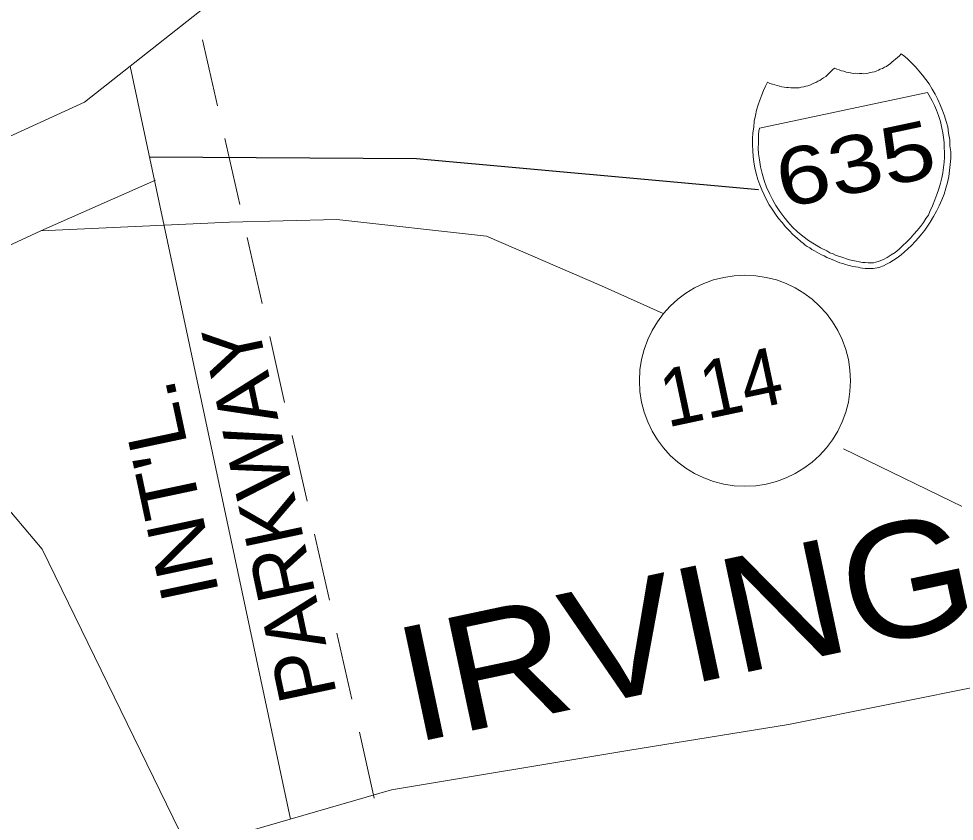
# Model space of a CAD drawing. Extents: x 2357218 to 2371708, y 6973728 to 6980157.
# Drawn here: x 2357598.1 to 2357681, y 6974748.1 to 6974819.3 of the extents above; entities that cross this region are included whole.
import ezdxf

# ---------------------------------------------------------------- set-up
doc = ezdxf.new("R2010")
doc.units = 0
doc.header["$LTSCALE"] = 2
doc.linetypes.add('MEDIUM_DASHED', pattern=[4.5, 3, -1.5])
doc.layers.add('62', color=7, linetype='Continuous', lineweight=13)
doc.layers.add('63', color=7, linetype='Continuous', lineweight=13)

msp = doc.modelspace()

# ---------------------------------------------------------------- linework, layer by layer
at = {"layer": '62', "linetype": 'MEDIUM_DASHED'}
msp.add_line((2357608.391, 6974843.78), (2357670.463, 6974569.716), dxfattribs=at)
at = {"layer": '62'}
for p, q in [((2357622.155, 6974748.291), (2357607.952, 6974815.115)), ((2357600.015, 6974800.5), (2357610.198, 6974804.988)), ((2357649.756, 6974795.612), (2357655.227, 6974793.141)), ((2357691.251, 6974771.4), (2357671.217, 6974781.127))]:
    msp.add_line(p, q, dxfattribs=at)
for points in [[(2357587.853, 6974800.146), (2357596.85, 6974808.683), (2357603.892, 6974811.906), (2357617.998, 6974823.047)], [(2357671.247, 6974814.652), (2357671.444, 6974814.579), (2357671.661, 6974814.533), (2357671.829, 6974814.499), (2357672.069, 6974814.457), (2357672.25, 6974814.474), (2357672.445, 6974814.424), (2357672.625, 6974814.44), (2357672.832, 6974814.437), (2357673.018, 6974814.431), (2357673.222, 6974814.451), (2357673.398, 6974814.488), (2357673.594, 6974814.53), (2357673.77, 6974814.566), (2357673.969, 6974814.61), (2357674.164, 6974814.673), (2357674.329, 6974814.754), (2357674.474, 6974814.831), (2357674.667, 6974814.896), (2357674.846, 6974815.026), (2357675.017, 6974815.085), (2357675.196, 6974815.214), (2357675.358, 6974815.319), (2357675.515, 6974815.444), (2357675.692, 6974815.596), (2357675.828, 6974815.716), (2357676.002, 6974815.87), (2357676.176, 6974816.02), (2357676.324, 6974816.191), (2357676.647, 6974815.959), (2357676.962, 6974815.682), (2357677.277, 6974815.381), (2357677.604, 6974815.036), (2357677.909, 6974814.687), (2357678.217, 6974814.317), (2357678.532, 6974813.922), (2357678.801, 6974813.52), (2357679.085, 6974813.05), (2357679.336, 6974812.622), (2357679.577, 6974812.143), (2357679.794, 6974811.659), (2357679.991, 6974811.174), (2357680.185, 6974810.686), (2357680.31, 6974810.205), (2357680.462, 6974809.709), (2357680.534, 6974809.148), (2357680.636, 6974808.574), (2357680.658, 6974808.027), (2357680.727, 6974807.489), (2357680.73, 6974806.938), (2357680.664, 6974806.372), (2357680.615, 6974805.853), (2357680.546, 6974805.311), (2357680.428, 6974804.779), (2357680.284, 6974804.266), (2357680.14, 6974803.75), (2357679.948, 6974803.25), (2357679.717, 6974802.718), (2357679.474, 6974802.229), (2357679.208, 6974801.757), (2357678.9, 6974801.255), (2357678.677, 6974800.908), (2357678.428, 6974800.557), (2357678.137, 6974800.196), (2357677.863, 6974799.862), (2357677.56, 6974799.542), (2357677.244, 6974799.201), (2357676.916, 6974798.901), (2357676.61, 6974798.606), (2357676.319, 6974798.362), (2357675.981, 6974798.104), (2357675.664, 6974797.874), (2357675.333, 6974797.691), (2357675.045, 6974797.535), (2357674.754, 6974797.383), (2357674.454, 6974797.274), (2357674.192, 6974797.217)], [(2357674.192, 6974797.217), (2357674.014, 6974797.18), (2357673.859, 6974797.147), (2357673.674, 6974797.152), (2357673.517, 6974797.143), (2357673.331, 6974797.151), (2357673.146, 6974797.156), (2357672.911, 6974797.176), (2357672.697, 6974797.2), (2357672.506, 6974797.251), (2357672.288, 6974797.297), (2357672.049, 6974797.336), (2357671.834, 6974797.382), (2357671.588, 6974797.447), (2357671.393, 6974797.497), (2357671.146, 6974797.583), (2357670.901, 6974797.646), (2357670.678, 6974797.735), (2357670.424, 6974797.841), (2357670.198, 6974797.933), (2357669.97, 6974798.023), (2357669.742, 6974798.134), (2357669.505, 6974798.27), (2357669.28, 6974798.358), (2357669.069, 6974798.475), (2357668.839, 6974798.586), (2357668.631, 6974798.704), (2357668.416, 6974798.842), (2357668.224, 6974798.986), (2357667.994, 6974799.097), (2357667.807, 6974799.217), (2357667.66, 6974799.37), (2357667.443, 6974799.532), (2357667.103, 6974799.827), (2357666.732, 6974800.165), (2357666.401, 6974800.532), (2357666.079, 6974800.855), (2357665.768, 6974801.227), (2357665.439, 6974801.595), (2357665.174, 6974801.976), (2357664.9, 6974802.4), (2357664.628, 6974802.803), (2357664.397, 6974803.234), (2357664.191, 6974803.674), (2357663.981, 6974804.113), (2357663.793, 6974804.578), (2357663.623, 6974805.049), (2357663.466, 6974805.567), (2357663.358, 6974806.074), (2357663.272, 6974806.585), (2357663.214, 6974807.079), (2357663.173, 6974807.599), (2357663.153, 6974808.124), (2357663.155, 6974808.654), (2357663.179, 6974809.188), (2357663.257, 6974809.686), (2357663.303, 6974810.226), (2357663.411, 6974810.709), (2357663.513, 6974811.191), (2357663.646, 6974811.656), (2357663.781, 6974812.098), (2357663.961, 6974812.551), (2357664.107, 6974812.949), (2357664.301, 6974813.335), (2357664.483, 6974813.673), (2357664.685, 6974813.578), (2357664.931, 6974813.516), (2357665.129, 6974813.442), (2357665.323, 6974813.395), (2357665.544, 6974813.325), (2357665.741, 6974813.275), (2357665.953, 6974813.25), (2357666.147, 6974813.2), (2357666.328, 6974813.214), (2357666.545, 6974813.168), (2357666.725, 6974813.185), (2357666.932, 6974813.183), (2357667.139, 6974813.181), (2357667.298, 6974813.191), (2357667.474, 6974813.229), (2357667.695, 6974813.276), (2357667.871, 6974813.314), (2357668.048, 6974813.35), (2357668.24, 6974813.416), (2357668.409, 6974813.496), (2357668.576, 6974813.579), (2357668.767, 6974813.64), (2357668.946, 6974813.77), (2357669.117, 6974813.831), (2357669.274, 6974813.956), (2357669.439, 6974814.059), (2357669.639, 6974814.193), (2357669.792, 6974814.342), (2357669.949, 6974814.468), (2357670.104, 6974814.615), (2357670.256, 6974814.764), (2357670.424, 6974814.937), (2357670.628, 6974814.843), (2357670.827, 6974814.77), (2357671.048, 6974814.701), (2357671.247, 6974814.652)], [(2357587.457, 6974794.656), (2357600.015, 6974800.5), (2357616.764, 6974801.254)], [(2357616.764, 6974801.254), (2357626.286, 6974801.484), (2357639.552, 6974800.002), (2357649.756, 6974795.612)], [(2357612.906, 6974746.026), (2357600.131, 6974772.25), (2357585.724, 6974789.274)], [(2357595.779, 6974740.777), (2357608.657, 6974744.365), (2357631.126, 6974750.887), (2357652.256, 6974754.413), (2357666.337, 6974756.671), (2357684.011, 6974760.219), (2357693.6, 6974764.79), (2357703.731, 6974774.259), (2357715.298, 6974783.597), (2357718.976, 6974785.553)]]:
    msp.add_lwpolyline(points, dxfattribs=at)
msp.add_lwpolyline([(2357678.664, 6974812.754), (2357663.762, 6974809.587), (2357663.721, 6974809.347), (2357663.69, 6974809.064), (2357663.667, 6974808.738), (2357663.667, 6974808.303), (2357663.65, 6974807.837), (2357663.664, 6974807.335), (2357663.76, 6974806.781), (2357663.867, 6974806.182), (2357664.017, 6974805.569), (2357664.17, 6974804.957), (2357664.389, 6974804.36), (2357664.648, 6974803.795), (2357664.924, 6974803.256), (2357665.217, 6974802.744), (2357665.56, 6974802.218), (2357665.915, 6974801.741), (2357666.286, 6974801.291), (2357666.686, 6974800.823), (2357667.14, 6974800.413), (2357667.595, 6974800.002), (2357668.112, 6974799.63), (2357668.641, 6974799.305), (2357669.168, 6974798.979), (2357669.733, 6974798.708), (2357670.001, 6974798.535), (2357670.297, 6974798.438), (2357670.575, 6974798.313), (2357670.896, 6974798.22), (2357671.169, 6974798.115), (2357671.471, 6974797.996), (2357671.763, 6974797.921), (2357672.055, 6974797.843), (2357672.342, 6974797.791), (2357672.608, 6974797.733), (2357672.896, 6974797.679), (2357673.152, 6974797.665), (2357673.41, 6974797.648), (2357673.638, 6974797.652), (2357673.866, 6974797.655), (2357674.087, 6974797.702), (2357674.392, 6974797.789), (2357674.754, 6974797.933), (2357675.082, 6974798.12), (2357675.444, 6974798.358), (2357675.79, 6974798.57), (2357676.14, 6974798.874), (2357676.467, 6974799.174), (2357676.818, 6974799.476), (2357677.157, 6974799.824), (2357677.469, 6974800.191), (2357677.766, 6974800.529), (2357678.033, 6974800.887), (2357678.31, 6974801.221), (2357678.534, 6974801.569), (2357678.743, 6974801.887), (2357678.862, 6974802.191), (2357679.123, 6974802.706), (2357679.308, 6974803.23), (2357679.507, 6974803.709), (2357679.672, 6974804.229), (2357679.819, 6974804.72), (2357679.93, 6974805.179), (2357680.017, 6974805.636), (2357680.078, 6974806.109), (2357680.136, 6974806.579), (2357680.186, 6974807.006), (2357680.18, 6974807.465), (2357680.158, 6974807.896), (2357680.134, 6974808.329), (2357680.09, 6974808.757), (2357680.022, 6974809.18), (2357679.934, 6974809.597), (2357679.81, 6974810.19), (2357679.648, 6974810.732), (2357679.455, 6974811.197), (2357679.297, 6974811.623), (2357679.096, 6974812.019), (2357678.921, 6974812.302), (2357678.779, 6974812.548)], close=True, dxfattribs=at)
at = {"layer": '62', "lineweight": 25}
msp.add_lwpolyline([(2357663.677, 6974804.141), (2357633.331, 6974806.868), (2357609.673, 6974807.016)], dxfattribs=at)
at = {"layer": '62'}
msp.add_circle((2357662.477, 6974787.185), 9.364, dxfattribs=at)
at = {"layer": '63', "linetype": 'MEDIUM_DASHED'}
msp.add_line((2357608.391, 6974843.78), (2357670.463, 6974569.716), dxfattribs=at)
at = {"layer": '63'}
for p, q in [((2357622.155, 6974748.291), (2357607.952, 6974815.115)), ((2357600.015, 6974800.5), (2357610.198, 6974804.988)), ((2357649.756, 6974795.612), (2357655.227, 6974793.141)), ((2357691.251, 6974771.4), (2357671.217, 6974781.127))]:
    msp.add_line(p, q, dxfattribs=at)
for points in [[(2357587.853, 6974800.146), (2357596.85, 6974808.683), (2357603.892, 6974811.906), (2357617.998, 6974823.047)], [(2357671.247, 6974814.652), (2357671.444, 6974814.579), (2357671.661, 6974814.533), (2357671.829, 6974814.499), (2357672.069, 6974814.457), (2357672.25, 6974814.474), (2357672.445, 6974814.424), (2357672.625, 6974814.44), (2357672.832, 6974814.437), (2357673.018, 6974814.431), (2357673.222, 6974814.451), (2357673.398, 6974814.488), (2357673.594, 6974814.53), (2357673.77, 6974814.566), (2357673.969, 6974814.61), (2357674.164, 6974814.673), (2357674.329, 6974814.754), (2357674.474, 6974814.831), (2357674.667, 6974814.896), (2357674.846, 6974815.026), (2357675.017, 6974815.085), (2357675.196, 6974815.214), (2357675.358, 6974815.319), (2357675.515, 6974815.444), (2357675.692, 6974815.596), (2357675.828, 6974815.716), (2357676.002, 6974815.87), (2357676.176, 6974816.02), (2357676.324, 6974816.191), (2357676.647, 6974815.959), (2357676.962, 6974815.682), (2357677.277, 6974815.381), (2357677.604, 6974815.036), (2357677.909, 6974814.687), (2357678.217, 6974814.317), (2357678.532, 6974813.922), (2357678.801, 6974813.52), (2357679.085, 6974813.05), (2357679.336, 6974812.622), (2357679.577, 6974812.143), (2357679.794, 6974811.659), (2357679.991, 6974811.174), (2357680.185, 6974810.686), (2357680.31, 6974810.205), (2357680.462, 6974809.709), (2357680.534, 6974809.148), (2357680.636, 6974808.574), (2357680.658, 6974808.027), (2357680.727, 6974807.489), (2357680.73, 6974806.938), (2357680.664, 6974806.372), (2357680.615, 6974805.853), (2357680.546, 6974805.311), (2357680.428, 6974804.779), (2357680.284, 6974804.266), (2357680.14, 6974803.75), (2357679.948, 6974803.25), (2357679.717, 6974802.718), (2357679.474, 6974802.229), (2357679.208, 6974801.757), (2357678.9, 6974801.255), (2357678.677, 6974800.908), (2357678.428, 6974800.557), (2357678.137, 6974800.196), (2357677.863, 6974799.862), (2357677.56, 6974799.542), (2357677.244, 6974799.201), (2357676.916, 6974798.901), (2357676.61, 6974798.606), (2357676.319, 6974798.362), (2357675.981, 6974798.104), (2357675.664, 6974797.874), (2357675.333, 6974797.691), (2357675.045, 6974797.535), (2357674.754, 6974797.383), (2357674.454, 6974797.274), (2357674.192, 6974797.217)], [(2357674.192, 6974797.217), (2357674.014, 6974797.18), (2357673.859, 6974797.147), (2357673.674, 6974797.152), (2357673.517, 6974797.143), (2357673.331, 6974797.151), (2357673.146, 6974797.156), (2357672.911, 6974797.176), (2357672.697, 6974797.2), (2357672.506, 6974797.251), (2357672.288, 6974797.297), (2357672.049, 6974797.336), (2357671.834, 6974797.382), (2357671.588, 6974797.447), (2357671.393, 6974797.497), (2357671.146, 6974797.583), (2357670.901, 6974797.646), (2357670.678, 6974797.735), (2357670.424, 6974797.841), (2357670.198, 6974797.933), (2357669.97, 6974798.023), (2357669.742, 6974798.134), (2357669.505, 6974798.27), (2357669.28, 6974798.358), (2357669.069, 6974798.475), (2357668.839, 6974798.586), (2357668.631, 6974798.704), (2357668.416, 6974798.842), (2357668.224, 6974798.986), (2357667.994, 6974799.097), (2357667.807, 6974799.217), (2357667.66, 6974799.37), (2357667.443, 6974799.532), (2357667.103, 6974799.827), (2357666.732, 6974800.165), (2357666.401, 6974800.532), (2357666.079, 6974800.855), (2357665.768, 6974801.227), (2357665.439, 6974801.595), (2357665.174, 6974801.976), (2357664.9, 6974802.4), (2357664.628, 6974802.803), (2357664.397, 6974803.234), (2357664.191, 6974803.674), (2357663.981, 6974804.113), (2357663.793, 6974804.578), (2357663.623, 6974805.049), (2357663.466, 6974805.567), (2357663.358, 6974806.074), (2357663.272, 6974806.585), (2357663.214, 6974807.079), (2357663.173, 6974807.599), (2357663.153, 6974808.124), (2357663.155, 6974808.654), (2357663.179, 6974809.188), (2357663.257, 6974809.686), (2357663.303, 6974810.226), (2357663.411, 6974810.709), (2357663.513, 6974811.191), (2357663.646, 6974811.656), (2357663.781, 6974812.098), (2357663.961, 6974812.551), (2357664.107, 6974812.949), (2357664.301, 6974813.335), (2357664.483, 6974813.673), (2357664.685, 6974813.578), (2357664.931, 6974813.516), (2357665.129, 6974813.442), (2357665.323, 6974813.395), (2357665.544, 6974813.325), (2357665.741, 6974813.275), (2357665.953, 6974813.25), (2357666.147, 6974813.2), (2357666.328, 6974813.214), (2357666.545, 6974813.168), (2357666.725, 6974813.185), (2357666.932, 6974813.183), (2357667.139, 6974813.181), (2357667.298, 6974813.191), (2357667.474, 6974813.229), (2357667.695, 6974813.276), (2357667.871, 6974813.314), (2357668.048, 6974813.35), (2357668.24, 6974813.416), (2357668.409, 6974813.496), (2357668.576, 6974813.579), (2357668.767, 6974813.64), (2357668.946, 6974813.77), (2357669.117, 6974813.831), (2357669.274, 6974813.956), (2357669.439, 6974814.059), (2357669.639, 6974814.193), (2357669.792, 6974814.342), (2357669.949, 6974814.468), (2357670.104, 6974814.615), (2357670.256, 6974814.764), (2357670.424, 6974814.937), (2357670.628, 6974814.843), (2357670.827, 6974814.77), (2357671.048, 6974814.701), (2357671.247, 6974814.652)], [(2357587.457, 6974794.656), (2357600.015, 6974800.5), (2357616.764, 6974801.254)], [(2357616.764, 6974801.254), (2357626.286, 6974801.484), (2357639.552, 6974800.002), (2357649.756, 6974795.612)], [(2357612.906, 6974746.026), (2357600.131, 6974772.25), (2357585.724, 6974789.274)], [(2357595.779, 6974740.777), (2357608.657, 6974744.365), (2357631.126, 6974750.887), (2357652.256, 6974754.413), (2357666.337, 6974756.671), (2357684.011, 6974760.219), (2357693.6, 6974764.79), (2357703.731, 6974774.259), (2357715.298, 6974783.597), (2357718.976, 6974785.553)]]:
    msp.add_lwpolyline(points, dxfattribs=at)
msp.add_lwpolyline([(2357678.664, 6974812.754), (2357663.762, 6974809.587), (2357663.721, 6974809.347), (2357663.69, 6974809.064), (2357663.667, 6974808.738), (2357663.667, 6974808.303), (2357663.65, 6974807.837), (2357663.664, 6974807.335), (2357663.76, 6974806.781), (2357663.867, 6974806.182), (2357664.017, 6974805.569), (2357664.17, 6974804.957), (2357664.389, 6974804.36), (2357664.648, 6974803.795), (2357664.924, 6974803.256), (2357665.217, 6974802.744), (2357665.56, 6974802.218), (2357665.915, 6974801.741), (2357666.286, 6974801.291), (2357666.686, 6974800.823), (2357667.14, 6974800.413), (2357667.595, 6974800.002), (2357668.112, 6974799.63), (2357668.641, 6974799.305), (2357669.168, 6974798.979), (2357669.733, 6974798.708), (2357670.001, 6974798.535), (2357670.297, 6974798.438), (2357670.575, 6974798.313), (2357670.896, 6974798.22), (2357671.169, 6974798.115), (2357671.471, 6974797.996), (2357671.763, 6974797.921), (2357672.055, 6974797.843), (2357672.342, 6974797.791), (2357672.608, 6974797.733), (2357672.896, 6974797.679), (2357673.152, 6974797.665), (2357673.41, 6974797.648), (2357673.638, 6974797.652), (2357673.866, 6974797.655), (2357674.087, 6974797.702), (2357674.392, 6974797.789), (2357674.754, 6974797.933), (2357675.082, 6974798.12), (2357675.444, 6974798.358), (2357675.79, 6974798.57), (2357676.14, 6974798.874), (2357676.467, 6974799.174), (2357676.818, 6974799.476), (2357677.157, 6974799.824), (2357677.469, 6974800.191), (2357677.766, 6974800.529), (2357678.033, 6974800.887), (2357678.31, 6974801.221), (2357678.534, 6974801.569), (2357678.743, 6974801.887), (2357678.862, 6974802.191), (2357679.123, 6974802.706), (2357679.308, 6974803.23), (2357679.507, 6974803.709), (2357679.672, 6974804.229), (2357679.819, 6974804.72), (2357679.93, 6974805.179), (2357680.017, 6974805.636), (2357680.078, 6974806.109), (2357680.136, 6974806.579), (2357680.186, 6974807.006), (2357680.18, 6974807.465), (2357680.158, 6974807.896), (2357680.134, 6974808.329), (2357680.09, 6974808.757), (2357680.022, 6974809.18), (2357679.934, 6974809.597), (2357679.81, 6974810.19), (2357679.648, 6974810.732), (2357679.455, 6974811.197), (2357679.297, 6974811.623), (2357679.096, 6974812.019), (2357678.921, 6974812.302), (2357678.779, 6974812.548)], close=True, dxfattribs=at)
at = {"layer": '63', "lineweight": 25}
msp.add_lwpolyline([(2357663.677, 6974804.141), (2357633.331, 6974806.868), (2357609.673, 6974807.016)], dxfattribs=at)
at = {"layer": '63'}
msp.add_circle((2357662.477, 6974787.185), 9.364, dxfattribs=at)

# ---------------------------------------------------------------- texts
at = {"layer": '62'}
for s, height, rotation, width, p in [('635', 5.099, 12, 1.25, (2357665.83, 6974802.46)), ('114', 5.099, 12, 0.95, (2357655.584, 6974783.027)), ("INT'L.", 5.099, 102, 1.1, (2357615.867, 6974768.259)), ('IRVING', 10.21, 12, 1.1, (2357633.011, 6974755.016))]:
    msp.add_text(s, height=height, rotation=rotation, dxfattribs=dict(at, width=width)).set_placement(p)
msp.add_text('PARKWAY', height=5.099, rotation=102, dxfattribs=at).set_placement((2357626.299, 6974759.32))
at = {"layer": '63'}
for s, height, rotation, width, p in [('635', 5.099, 12, 1.25, (2357665.83, 6974802.46)), ('114', 5.099, 12, 0.95, (2357655.584, 6974783.027)), ("INT'L.", 5.099, 102, 1.1, (2357615.867, 6974768.259)), ('IRVING', 10.21, 12, 1.1, (2357633.011, 6974755.016))]:
    msp.add_text(s, height=height, rotation=rotation, dxfattribs=dict(at, width=width)).set_placement(p)
msp.add_text('PARKWAY', height=5.099, rotation=102, dxfattribs=at).set_placement((2357626.299, 6974759.32))

doc.saveas('drawing.dxf')
